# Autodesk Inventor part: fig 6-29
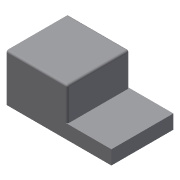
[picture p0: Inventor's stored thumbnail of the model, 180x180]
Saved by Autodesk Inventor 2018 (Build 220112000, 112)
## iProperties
Created: 2004-05
Part Number: fig 6-29
Document SubType Name: Modeling
Designer: CADCIM Technologies
Manufacturer: Standard
Standards Organization: Custom
Density: 1 g/cm^3
Material: Generic
Appearance: Default
Author: CADCIM Technologies
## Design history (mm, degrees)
node "Sketch1"
sketch "Sketch2"
  geometry: L1 (0.098, 47.711)-(0.098, 0.049); L2 (0.098, 0.049)-(-105.483, 0.049); L3 (-105.483, 0.049)-(-105.483, 14.192); L4 (-105.483, 14.192)-(-61.139, 14.192); L5 (-61.139, 14.192)-(-61.139, 47.711); L6 (-61.139, 47.711)-(0.098, 47.711)
  constraints: 12 end point, 3 parallel, 2 perpendicular, 1 vertical
extrude "Extrusion1" new body sketch "Sketch2" stored distance "d0" = 62.5; taper "d1" = 0 deg
fillet "Fillet6" dims "d44" = 2, "d45" = 2, "d46" = 2, "d47" = 2, "d48" = 2, "d49" = 2
body "Solid1"
